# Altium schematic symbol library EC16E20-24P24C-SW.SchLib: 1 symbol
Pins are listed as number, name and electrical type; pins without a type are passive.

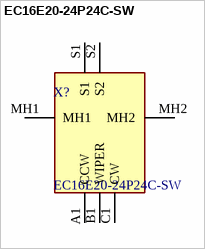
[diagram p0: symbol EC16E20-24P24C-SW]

## EC16E20-24P24C-SW
designator X?
Specification ; Resolution. 24imp/revol. ; Number of positions. 24 ; Output signal. two phase A and B ; Mechanical durability. 50000 cycles ; Operating voltage. 5V ..; Manufacturer_Name: SRPASSIVES; Geometry.Height: 28mm
footprint EC16E2024P24CSW
pins: A1 CCW, B1 WIPER, C1 CW, MH1, MH2, S1, S2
